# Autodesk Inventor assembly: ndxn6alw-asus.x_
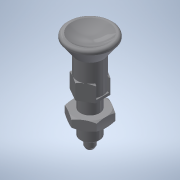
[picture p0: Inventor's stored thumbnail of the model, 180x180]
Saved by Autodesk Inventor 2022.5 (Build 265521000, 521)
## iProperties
Part Number: ndxn6alw-asus.x_
Material: 一般
Document SubType Name: Assembly
Designer: ImaoCorp
Sending System: SOLIDWORKS 2017-2017317
MC: AMD64
MC_MODEL: Intel64 Family 6 Model 60 Stepping 3, GenuineIntel
OS: Windows_NT
FRU: Parasolid Version 29.0, build 201,  4-17-2017
FORMAT: text
GUISE: transmit
KEY: ndxn6alw-asus
FILE: ndxn6alw-asus.x_t
DATE: Wed Sep 04 15:27:54 2019
Author: ImaoCorp
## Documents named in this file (3)
- X:\14_SW2022-Inv2022\00_全2023-1023新製品(TCC)まで\n\ndxn6alw-asus\NDXN6ALW-ASUS.iam
- X:\14_SW2022-Inv2022\00_全2023-1023新製品(TCC)まで\n\ndxn6alw-asus\ndxn6alw-asus_01.ipt
- X:\14_SW2022-Inv2022\00_全2023-1023新製品(TCC)まで\n\ndxn6alw-asus\ndxn6alw-asus_02.ipt
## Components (2 placed, 2 different names)
1. ndxn6alw-asus_01
2. ndxn6alw-asus_02
